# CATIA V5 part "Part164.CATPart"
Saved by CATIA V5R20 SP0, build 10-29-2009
Part number: DFA 105700-3
Revision: ANY
Definition: UNKNOWN
Nomenclature: DFA 105700-3
Source: Unknown
Bounding box of the stored display mesh (mm): x -2.687 to 2.687, y -2.475 to 2.475, z -2.5 to 2.5
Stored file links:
  C:\Users\Utente\Desktop\IO LAVORO\3D X SITO CF\CUMSA\3D files FA\FA 105712-21\Part164.CATPart
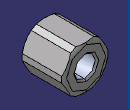
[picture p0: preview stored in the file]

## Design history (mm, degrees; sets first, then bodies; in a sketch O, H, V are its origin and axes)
Body1 "Chaflán4" (main body)
  Solid1: solid without history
